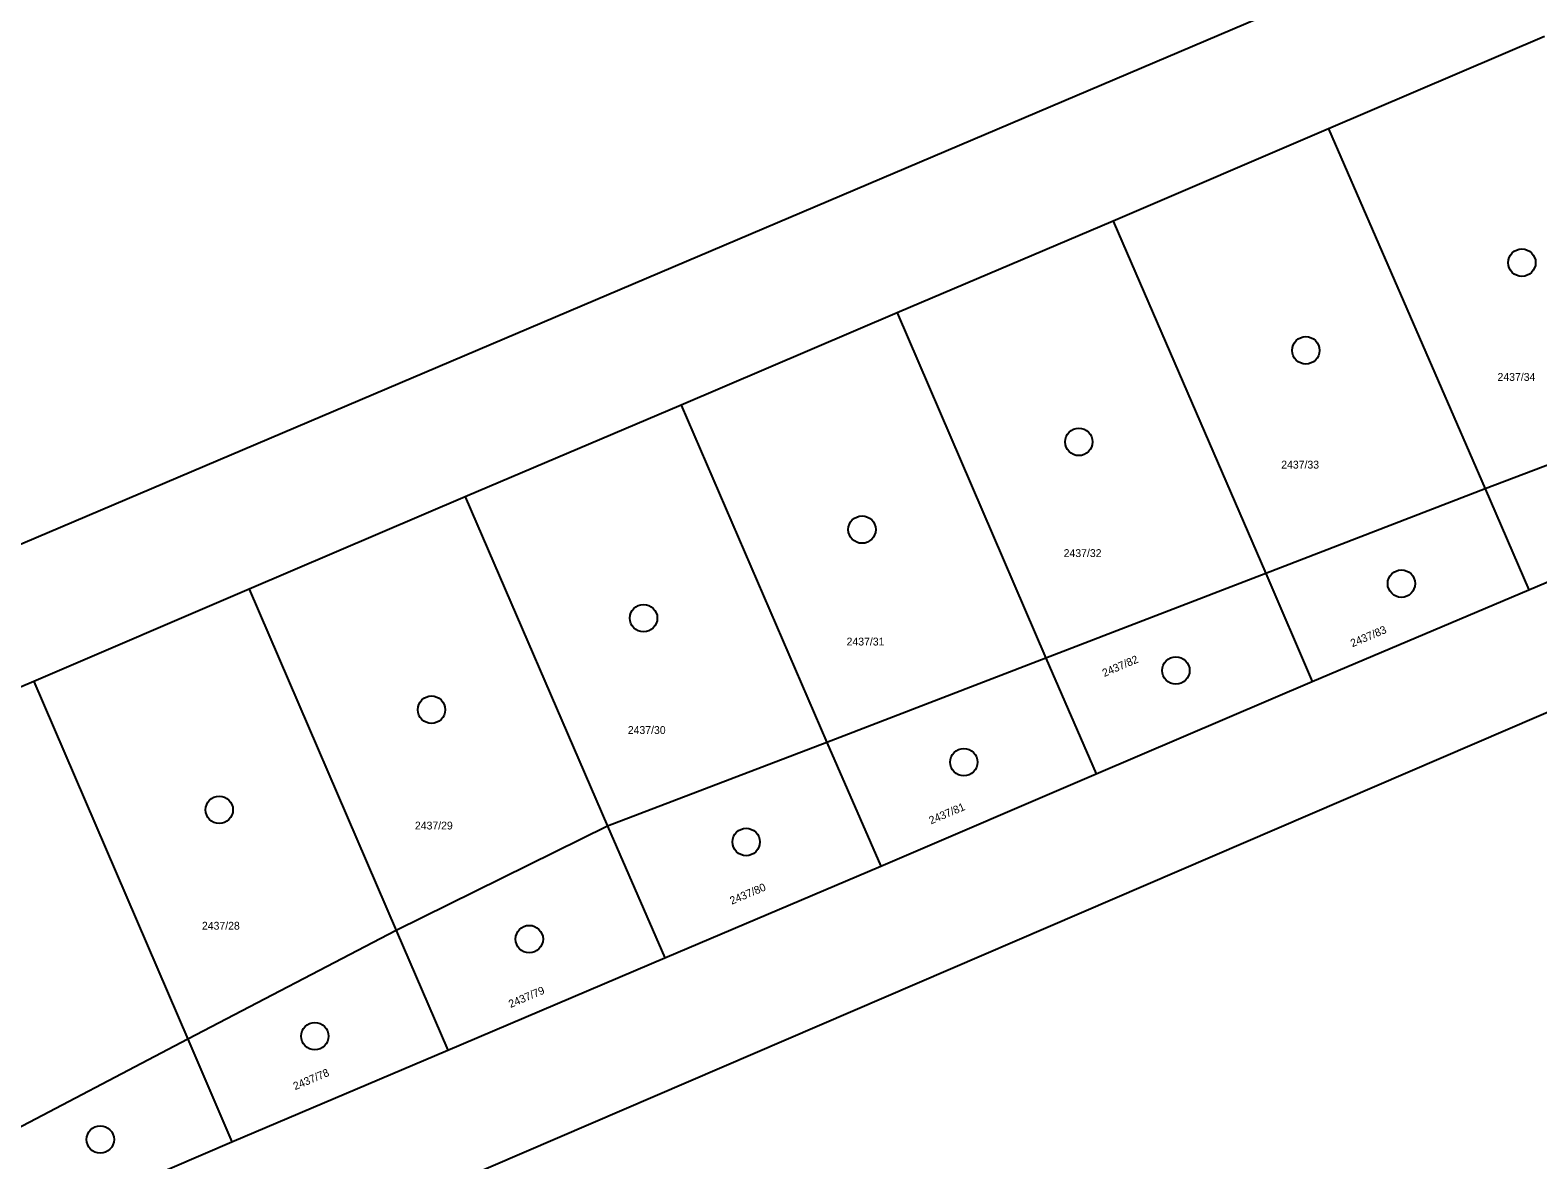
# Model space of a CAD drawing. Extents: x -822293 to -820259, y -1071573 to -1068794.
# Drawn here: x -820538.68 to -820519.42, y -1069594.98 to -1069580.55 of the extents above; entities that cross this region are included whole.
import ezdxf

# ---------------------------------------------------------------- set-up
doc = ezdxf.new("R2010")
doc.units = 0
for name, color, linetype in [('Vrstva 1', 7, 'Continuous'), ('Vrstva 10', 7, 'Continuous'), ('Vrstva 16', 7, 'Continuous'), ('Vrstva 19', 7, 'Continuous'), ('Vrstva 25', 7, 'Continuous')]:
    doc.layers.add(name, color=color, linetype=linetype)

msp = doc.modelspace()

# ---------------------------------------------------------------- linework, layer by layer
at = {"layer": 'Vrstva 1'}
for p, q in [((-820519.33, -1069580.63), (-820522.09, -1069581.81)), ((-820522.09, -1069581.81), (-820524.84, -1069582.99)), ((-820522.09, -1069581.81), (-820520.09, -1069586.41)), ((-820524.84, -1069582.99), (-820527.6, -1069584.16)), ((-820524.84, -1069582.99), (-820522.89, -1069587.49)), ((-820527.6, -1069584.16), (-820530.36, -1069585.34)), ((-820527.6, -1069584.16), (-820525.7, -1069588.57)), ((-820530.36, -1069585.34), (-820533.12, -1069586.51)), ((-820530.36, -1069585.34), (-820528.5, -1069589.65)), ((-820517.32, -1069585.35), (-820520.09, -1069586.41)), ((-820533.12, -1069586.51), (-820535.88, -1069587.69)), ((-820533.12, -1069586.51), (-820531.3, -1069590.72)), ((-820520.09, -1069586.41), (-820522.89, -1069587.49)), ((-820520.09, -1069586.41), (-820519.53, -1069587.7)), ((-820519.53, -1069587.7), (-820516.77, -1069586.52)), ((-820522.89, -1069587.49), (-820525.7, -1069588.57)), ((-820522.89, -1069587.49), (-820522.3, -1069588.87)), ((-820535.88, -1069587.69), (-820538.63, -1069588.87)), ((-820535.88, -1069587.69), (-820534, -1069592.05)), ((-820522.3, -1069588.87), (-820519.53, -1069587.7)), ((-820525.7, -1069588.57), (-820528.5, -1069589.65)), ((-820525.7, -1069588.57), (-820525.06, -1069590.05)), ((-820538.63, -1069588.87), (-820541.39, -1069590.04)), ((-820538.63, -1069588.87), (-820536.66, -1069593.44)), ((-820525.06, -1069590.05), (-820522.3, -1069588.87)), ((-820528.5, -1069589.65), (-820531.3, -1069590.72)), ((-820528.5, -1069589.65), (-820527.81, -1069591.23)), ((-820527.81, -1069591.23), (-820525.06, -1069590.05)), ((-820531.3, -1069590.72), (-820534, -1069592.05)), ((-820531.3, -1069590.72), (-820530.57, -1069592.4)), ((-820530.57, -1069592.4), (-820527.81, -1069591.23)), ((-820534, -1069592.05), (-820536.66, -1069593.44)), ((-820534, -1069592.05), (-820533.34, -1069593.58)), ((-820533.34, -1069593.58), (-820530.57, -1069592.4)), ((-820536.66, -1069593.44), (-820539.47, -1069594.91)), ((-820536.66, -1069593.44), (-820536.1, -1069594.75)), ((-820536.1, -1069594.75), (-820533.34, -1069593.58)), ((-820539.04, -1069596.01), (-820536.1, -1069594.75))]:
    msp.add_line(p, q, dxfattribs=at)
at = {"layer": 'Vrstva 10'}
for points in [[(-820396.61, -1069576.94), (-820402.69, -1069578.49), (-820405.27, -1069579.21), (-820406.43, -1069579.53), (-820438.24, -1069587.5), (-820457.43, -1069592.39), (-820477.68, -1069597.79), (-820496.15, -1069603.16), (-820515.37, -1069609.41), (-820535.3, -1069616.98), (-820554.11, -1069625.3), (-820571.83, -1069634.26), (-820585.28, -1069641.81), (-820606.27, -1069655.04), (-820628.29, -1069671.01), (-820647.93, -1069687.34), (-820667.41, -1069705.6), (-820680.13, -1069718.49), (-820694.73, -1069734.03), (-820703.98, -1069744.22)], [(-820699.99, -1069747.07), (-820686.76, -1069732.45), (-820676.49, -1069721.48), (-820664.13, -1069708.83), (-820651.61, -1069696.85), (-820636.83, -1069683.83), (-820625.37, -1069674.56), (-820604.01, -1069659.07), (-820586.04, -1069647.64), (-820569.6, -1069638.45), (-820551.99, -1069629.79), (-820532.99, -1069621.67), (-820513.48, -1069614.48), (-820494.57, -1069608.43), (-820474.72, -1069602.78), (-820455.51, -1069597.69), (-820435.43, -1069592.58), (-820405.44, -1069585), (-820404.29, -1069584.71), (-820401.25, -1069583.95), (-820395.38, -1069582.43)]]:
    msp.add_spline(points, degree=3, dxfattribs=at)
at = {"layer": 'Vrstva 16'}
for p, q in [((-820578.78, -1069604.11), (-820441.76, -1069545.87)), ((-820536.81, -1069596.79), (-820503.78, -1069582.59))]:
    msp.add_line(p, q, dxfattribs=at)
at = {"layer": 'Vrstva 25'}
for centre in [(-820519.62, -1069583.52), (-820522.38, -1069584.64), (-820525.28, -1069585.81), (-820528.05, -1069586.93), (-820521.16, -1069587.62), (-820530.84, -1069588.06), (-820524.04, -1069588.73), (-820533.55, -1069589.23), (-820526.75, -1069589.9), (-820536.26, -1069590.51), (-820529.53, -1069590.92), (-820532.3, -1069592.16), (-820535.04, -1069593.4), (-820537.78, -1069594.72)]:
    msp.add_circle(centre, 0.175, dxfattribs=at)

# ---------------------------------------------------------------- texts
at = {"layer": 'Vrstva 19'}
for s, p in [('2437/34', (-820519.932, -1069585.03)), ('2437/33', (-820522.695, -1069586.15)), ('2437/32', (-820525.474, -1069587.28)), ('2437/31', (-820528.247, -1069588.41)), ('2437/30', (-820531.042, -1069589.54)), ('2437/29', (-820533.761, -1069590.76)), ('2437/28', (-820536.482, -1069592.04))]:
    msp.add_text(s, height=0.1, dxfattribs=at).set_placement(p)
for s, rotation, p in [('2437/83', 22.9183, (-820521.785, -1069588.433)), ('2437/82', 23.1475, (-820524.955, -1069588.813)), ('2437/81', 22.9757, (-820527.169, -1069590.696)), ('2437/80', 22.9757, (-820529.713, -1069591.722)), ('2437/79', 23.0902, (-820532.539, -1069593.041)), ('2437/78', 22.9757, (-820535.291, -1069594.091))]:
    msp.add_text(s, height=0.1, rotation=rotation, dxfattribs=at).set_placement(p)

doc.saveas('drawing.dxf')
